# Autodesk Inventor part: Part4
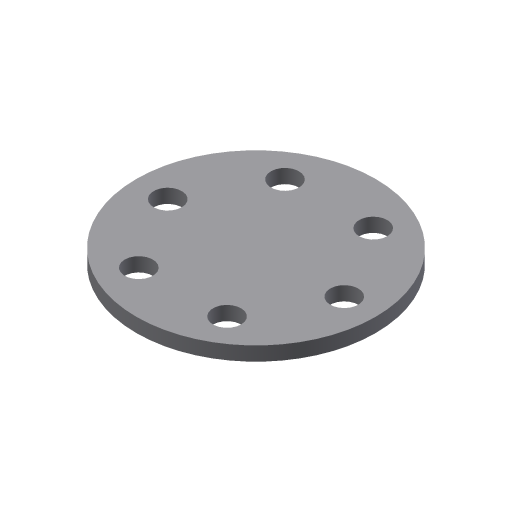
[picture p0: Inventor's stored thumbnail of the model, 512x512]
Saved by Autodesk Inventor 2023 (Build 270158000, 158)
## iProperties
Created: 2008-05
Part Number: Part4
Document SubType Name: Modeling
Designer: CADCIM
Density: 1 g/cm^3
Material: Generic
Appearance: Default
Author: CADCIM
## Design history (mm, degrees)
sketch "Sketch1"
  geometry: C1 r 17 at (0, 0)
  constraints: 1 centre point, 1 other
  dimensions: "d12" = 34 diameter of C1
extrude "Extrusion1" new body sketch "Sketch1" distance "d0" = 2; taper "d1" = 0 deg
sketch "Sketch2"
  geometry: 1 further point
hole "Hole1" sketch "Sketch2" at (5.9, 10.769) diameter "d2" = 4; stored, may be unused: countersink angle "d6" = 90 deg, drill point angle "d8" = 118 deg; dims "d3" = 6, "d4" = 4, "d5" = 2, "d7" = 8
pattern_circular "Circular Pattern1" dims angle "d10" = 360 deg
body "Solid1"
